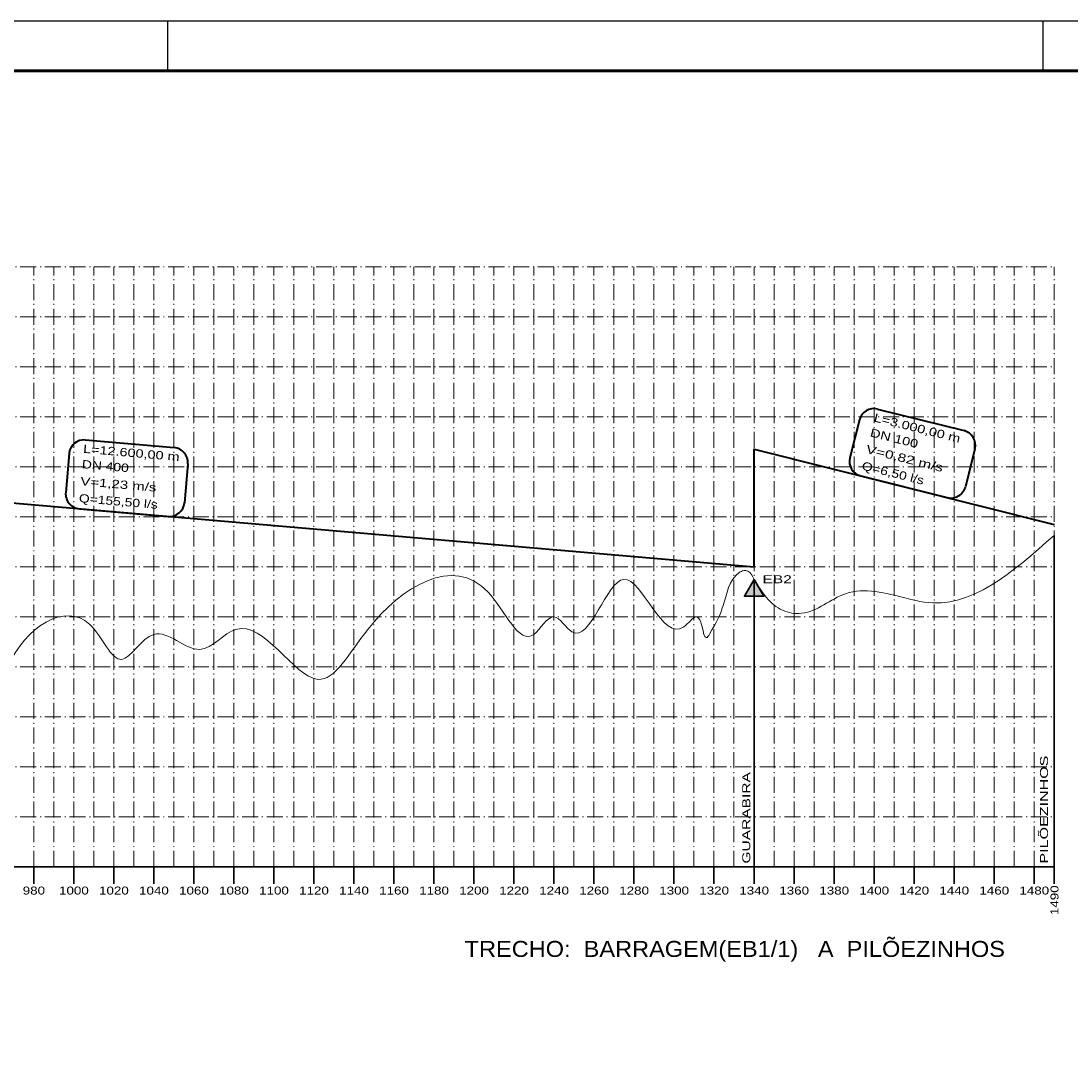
# Model space of a CAD drawing. Extents: x -4 to 42046, y -3 to 29697.
# Drawn here: x 22579 to 33074, y 19227 to 29697 of the extents above; entities that cross this region are included whole.
import ezdxf
from ezdxf.enums import TextEntityAlignment as Align

# ---------------------------------------------------------------- set-up
doc = ezdxf.new("R2010")
doc.units = 0
doc.header["$LTSCALE"] = 32
doc.linetypes.add('DOT_DASHED', pattern=[7.7, 5, -1.2, 0.3, -1.2])
for name, color, linetype, lineweight in [('1', 7, 'DOT_DASHED', 13), ('24', 7, 'Continuous', 35), ('55', 7, 'Continuous', 13), ('62', 7, 'Continuous', 13), ('63', 7, 'Continuous', 25), ('9', 7, 'Continuous', 40)]:
    doc.layers.add(name, color=color, linetype=linetype, lineweight=lineweight)

msp = doc.modelspace()

# ---------------------------------------------------------------- hatches: boundary and pattern name
at = {"layer": '62'}
msp.add_hatch(color=256, dxfattribs=at).paths.add_polyline_path([(29905.77, 24113.44), (30004.42, 23944.99), (29809.21, 23943.78)])

# ---------------------------------------------------------------- linework, layer by layer
at = {"layer": '1'}
for p, q in [((3105.77, 27238.44), (32905.77, 27238.44)), ((22705.77, 21238.44), (22705.77, 27238.44)), ((22905.77, 21238.44), (22905.77, 27238.44)), ((23105.77, 21238.44), (23105.77, 27238.44)), ((23305.77, 21238.44), (23305.77, 27238.44)), ((23505.77, 21238.44), (23505.77, 27238.44)), ((23705.77, 21238.44), (23705.77, 27238.44)), ((23905.77, 21238.44), (23905.77, 27238.44)), ((24105.77, 21238.44), (24105.77, 27238.44)), ((24305.77, 21238.44), (24305.77, 27238.44)), ((24505.77, 21238.44), (24505.77, 27238.44)), ((24705.77, 21238.44), (24705.77, 27238.44)), ((24905.77, 21238.44), (24905.77, 27238.44)), ((25105.77, 21238.44), (25105.77, 27238.44)), ((25305.77, 21238.44), (25305.77, 27238.44)), ((25505.77, 21238.44), (25505.77, 27238.44)), ((25705.77, 21238.44), (25705.77, 27238.44)), ((25905.77, 21238.44), (25905.77, 27238.44)), ((26105.77, 21238.44), (26105.77, 27238.44)), ((26305.77, 21238.44), (26305.77, 27238.44)), ((26505.77, 21238.44), (26505.77, 27238.44)), ((26705.77, 21238.44), (26705.77, 27238.44)), ((26905.77, 21238.44), (26905.77, 27238.44)), ((27105.77, 21238.44), (27105.77, 27238.44)), ((27305.77, 21238.44), (27305.77, 27238.44)), ((27505.77, 21238.44), (27505.77, 27238.44)), ((27705.77, 21238.44), (27705.77, 27238.44)), ((27905.77, 21238.44), (27905.77, 27238.44)), ((28105.77, 21238.44), (28105.77, 27238.44)), ((28305.77, 21238.44), (28305.77, 27238.44)), ((28505.77, 21238.44), (28505.77, 27238.44)), ((28705.77, 21238.44), (28705.77, 27238.44)), ((28905.77, 21238.44), (28905.77, 27238.44)), ((29105.77, 21238.44), (29105.77, 27238.44)), ((29305.77, 21238.44), (29305.77, 27238.44)), ((29505.77, 21238.44), (29505.77, 27238.44)), ((29705.77, 21238.44), (29705.77, 27238.44)), ((29905.77, 21238.44), (29905.77, 27238.44)), ((30105.77, 21238.44), (30105.77, 27238.44)), ((30305.77, 21238.44), (30305.77, 27238.44)), ((30505.77, 21238.44), (30505.77, 27238.44)), ((30705.77, 21238.44), (30705.77, 27238.44)), ((30905.77, 21238.44), (30905.77, 27238.44)), ((31105.77, 21238.44), (31105.77, 27238.44)), ((31305.77, 21238.44), (31305.77, 27238.44)), ((31505.77, 21238.44), (31505.77, 27238.44)), ((31705.77, 21238.44), (31705.77, 27238.44)), ((31905.77, 21238.44), (31905.77, 27238.44)), ((32105.77, 21238.44), (32105.77, 27238.44)), ((32305.77, 21238.44), (32305.77, 27238.44)), ((32505.77, 21238.44), (32505.77, 27238.44)), ((32705.77, 21238.44), (32705.77, 27238.44)), ((32905.77, 21238.44), (32905.77, 27238.44)), ((3105.77, 26738.44), (32905.77, 26738.44)), ((3105.77, 26238.44), (32905.77, 26238.44)), ((3105.77, 25738.44), (32905.77, 25738.44)), ((3105.77, 25238.44), (32905.77, 25238.44)), ((3105.77, 24738.44), (32905.77, 24738.44)), ((3105.77, 24238.44), (32905.77, 24238.44)), ((3105.77, 23738.44), (32905.77, 23738.44)), ((3105.77, 23238.44), (32905.77, 23238.44)), ((3105.77, 22738.44), (32905.77, 22738.44)), ((3105.77, 22238.44), (32905.77, 22238.44)), ((3105.77, 21738.44), (32905.77, 21738.44))]:
    msp.add_line(p, q, dxfattribs=at)
at = {"layer": '55', "lineweight": 35}
for p, q in [((32905.77, 24552.34), (32905.77, 21238.44)), ((29905.77, 24113.44), (29905.77, 21238.44))]:
    msp.add_line(p, q, dxfattribs=at)
at = {"layer": '55'}
for points in [[(29905.77, 24113.44), (30192.18, 23803.77), (30381.43, 23773.53), (30820.47, 23970.1), (31426.06, 23924.74), (31606.9, 23884.64), (32905.77, 24552.34)], [(3105.77, 22363.44), (3345.77, 22238.44), (3395.77, 22113.44), (3445.77, 22238.44), (3485.77, 22488.44), (3525.77, 22238.44), (3676.64, 22756.56), (3717.19, 22944.93), (3805.77, 23063.44), (3905.77, 22738.44), (3965.77, 22363.44), (4225.77, 23188.44), (4625.77, 22988.44), (5145.77, 21963.44), (6165.77, 22963.44), (6365.77, 22738.44), (6545.77, 22988.44), (6945.77, 23088.44), (7145.77, 23188.44), (7685.77, 23188.44), (8005.77, 22988.44), (8205.77, 22488.44), (8245.77, 22613.44), (8285.77, 22488.44), (8705.77, 22113.44), (9065.77, 22738.44), (9685.77, 23288.44), (10205.77, 23238.44), (10545.77, 23313.44), (11345.77, 23413.44), (11545.77, 23263.44), (12365.77, 23988.44), (12705.77, 23613.44), (12805.77, 23563.44), (13605.77, 23863.44), (13845.77, 23738.44), (13905.77, 23663.44), (14265.77, 24038.44), (14465.77, 24088.44), (14965.77, 23738.44), (15205.77, 23988.44), (15365.77, 23738.44), (15665.77, 23488.44), (15885.77, 23813.44), (16285.77, 23363.44), (16785.77, 22488.44), (16825.77, 22363.44), (16985.77, 22863.44), (17065.77, 22738.44), (17225.77, 22588.44), (17685.77, 22288.44), (17925.77, 22338.44), (18085.77, 22288.44), (18185.77, 22488.44), (18285.77, 22388.44), (18705.77, 22488.44), (18785.77, 22538.44), (18845.77, 22488.44), (19325.77, 22888.44), (19685.77, 22363.44), (20185.77, 22988.44), (20645.77, 23188.44), (21145.77, 22588.44), (21245.77, 22738.44), (21425.77, 22563.44), (21525.77, 22613.44), (21645.77, 22738.44), (21745.77, 22363.44), (21845.77, 22688.44), (22085.77, 22613.44), (22445.77, 23238.44), (23265.77, 23663.44), (23585.77, 23313.44), (23905.77, 23563.44), (24365.77, 23413.44), (24725.77, 23613.44), (25545.77, 23113.44), (26045.77, 23613.44), (27245.77, 23988.44), (27705.77, 23563.44), (27905.77, 23738.44), (28085.77, 23588.44), (28605.77, 24113.44), (29205.77, 23638.44), (29325.77, 23738.44), (29405.77, 23563.44)], [(29402.55, 23570.49), (29429.17, 23530.24), (29461.04, 23566.32), (29597.02, 23850.72), (29757.98, 24180.3), (29803.11, 24200.24), (29842.69, 24195.26), (29905.77, 24113.44)]]:
    msp.add_spline(points, degree=3, dxfattribs=at)
at = {"layer": '62', "lineweight": 35}
for p, q in [((22705.77, 21238.44), (22705.77, 21067.76)), ((23105.77, 21238.44), (23105.77, 21067.76)), ((23505.77, 21238.44), (23505.77, 21067.76)), ((23905.77, 21238.44), (23905.77, 21067.76)), ((24305.77, 21238.44), (24305.77, 21067.76)), ((24705.77, 21238.44), (24705.77, 21067.76)), ((25105.77, 21238.44), (25105.77, 21067.76)), ((25505.77, 21238.44), (25505.77, 21067.76)), ((25905.77, 21238.44), (25905.77, 21067.76)), ((26305.77, 21238.44), (26305.77, 21067.76)), ((26705.77, 21238.44), (26705.77, 21067.76)), ((27105.77, 21238.44), (27105.77, 21067.76)), ((27505.77, 21238.44), (27505.77, 21067.76)), ((27905.77, 21238.44), (27905.77, 21067.76)), ((28305.77, 21238.44), (28305.77, 21067.76)), ((28705.77, 21238.44), (28705.77, 21067.76)), ((29105.77, 21238.44), (29105.77, 21067.76)), ((29505.77, 21238.44), (29505.77, 21067.76)), ((29905.77, 21238.44), (29905.77, 21067.76)), ((29905.77, 21238.44), (32905.77, 21238.44)), ((30305.77, 21238.44), (30305.77, 21067.76)), ((30705.77, 21238.44), (30705.77, 21067.76)), ((31105.77, 21238.44), (31105.77, 21067.76)), ((31505.77, 21238.44), (31505.77, 21067.76)), ((31905.77, 21238.44), (31905.77, 21067.76)), ((32305.77, 21238.44), (32305.77, 21067.76)), ((32705.77, 21238.44), (32705.77, 21067.76)), ((32905.77, 21238.44), (32905.77, 21067.76))]:
    msp.add_line(p, q, dxfattribs=at)
msp.add_lwpolyline([(29905.77, 24113.44), (30004.42, 23944.99), (29809.21, 23943.78)], close=True, dxfattribs=at)
msp.add_lwpolyline([(3105.77, 21238.44), (10105.77, 21238.44), (29905.77, 21238.44)], dxfattribs=at)
at = {"layer": '63'}
for p, q in [((-4.21, 29697.03), (42045.8, 29697.03)), ((24045.8, 29197.03), (24045.8, 29697.03)), ((32795.79, 29197.03), (32795.79, 29697.03))]:
    msp.add_line(p, q, dxfattribs=at)
at = {"layer": '63', "lineweight": 60}
msp.add_lwpolyline([(1245.8, 29197.03), (41545.8, 29197.03), (41545.8, 497.03), (32795.79, 497.03)], dxfattribs=at)
at = {"layer": '9'}
for p, q in [((31141.29, 25816.69), (32005.48, 25600.36)), ((30959.36, 25707.6), (30864.59, 25329.02)), ((23221.25, 25507.27), (24108.81, 25430.79)), ((32114.57, 25418.43), (32019.8, 25039.85)), ((23058.93, 25370.7), (23025.42, 24981.88)), ((24245.38, 25268.46), (24211.88, 24879.64)), ((30973.68, 25147.08), (31837.86, 24930.76)), ((23161.99, 24819.56), (24049.55, 24743.07))]:
    msp.add_line(p, q, dxfattribs=at)
msp.add_lwpolyline([(3105.77, 26870.69), (4205.77, 26681.69), (17305.77, 25324.19), (29905.77, 24238.44), (29905.77, 25414.4), (32905.77, 24663.44)], dxfattribs=at)
for centre, start, end in [((31104.87, 25671.18), 75.94643, 165.94643), ((23208.37, 25357.82), 85.07494, 175.07494), ((31969.06, 25454.85), 345.94643, 75.94643), ((24095.93, 25281.34), 355.07494, 85.07494), ((31010.1, 25292.59), 165.94643, 255.94643), ((23174.87, 24969), 175.07494, 265.07494), ((31874.29, 25076.27), 255.94643, 345.94643), ((24062.43, 24892.52), 265.07494, 355.07494)]:
    msp.add_arc(centre, 150, start, end, dxfattribs=at)

# ---------------------------------------------------------------- texts
at = {"layer": '24', "width": 1.45}
msp.add_text('EB2', height=80, dxfattribs=at).set_placement((29990.82, 24074.5))
at = {"layer": '24'}
for s, width, p in [('PILÕEZINHOS', 1.5, (32844.77, 21271.36)), ('GUARABIRA', 1.45, (29868.45, 21271.36))]:
    msp.add_text(s, height=80, rotation=90, dxfattribs=dict(at, width=width)).set_placement(p)
for s, height, width, p in [('980', 80, 1.25, (22707.4, 20961.24)), ('1000', 80, 1.25, (23107.4, 20961.24)), ('1020', 80, 1.25, (23507.4, 20961.24)), ('1040', 80, 1.25, (23907.4, 20961.24)), ('1060', 80, 1.25, (24307.4, 20961.24)), ('1080', 80, 1.25, (24707.4, 20961.24)), ('1100', 80, 1.25, (25107.4, 20961.24)), ('1120', 80, 1.25, (25507.4, 20961.24)), ('1140', 80, 1.25, (25907.4, 20961.24)), ('1160', 80, 1.25, (26307.4, 20961.24)), ('1180', 80, 1.25, (26707.4, 20961.24)), ('1200', 80, 1.25, (27107.4, 20961.24)), ('1220', 80, 1.25, (27507.4, 20961.24)), ('1240', 80, 1.25, (27907.4, 20961.24)), ('1260', 80, 1.25, (28307.4, 20961.24)), ('1280', 80, 1.25, (28707.4, 20961.24)), ('1300', 80, 1.25, (29107.4, 20961.24)), ('1320', 80, 1.25, (29507.4, 20961.24)), ('1340', 80, 1.25, (29907.4, 20961.24)), ('1360', 80, 1.25, (30307.4, 20961.24)), ('1380', 80, 1.25, (30707.4, 20961.24)), ('1400', 80, 1.25, (31107.4, 20961.24)), ('1420', 80, 1.25, (31507.4, 20961.24)), ('1440', 80, 1.25, (31907.4, 20961.24)), ('1460', 80, 1.25, (32307.4, 20961.24)), ('1480', 80, 1.25, (32707.4, 20961.24)), ('TRECHO:  BARRAGEM(EB1/1)   A  PILÕEZINHOS', 160, 1.1, (29713.7, 20337.39))]:
    msp.add_text(s, height=height, dxfattribs=dict(at, width=width)).set_placement(p, align=Align.CENTER)
at = {"layer": '24', "width": 1.25}
msp.add_text('1490', height=80, rotation=90, dxfattribs=at).set_placement((32949.09, 20904.33), align=Align.CENTER)
at = {"layer": '9'}
for s, rotation, width, p in [('L=3.000,00 m', 345.946, 1.3, (31097.36, 25694.22)), ('DN 100', 345.946, 1.3, (31059.84, 25544.35)), ('L=12.600,00 m', 355.075, 1.3, (23197.3, 25379.39)), ('V=0,82 m/s', 345.946, 1.4, (31018.42, 25378.87)), ('DN 400', 355.075, 1.25, (23184.04, 25225.46)), ('Q=6,50 l/s', 345.946, 1.25, (30977, 25213.39)), ('V=1,23 m/s', 355.075, 1.35, (23169.39, 25055.5)), ('Q=155,50 l/s', 355.075, 1.25, (23154.75, 24885.54))]:
    msp.add_text(s, height=82.98, rotation=rotation, dxfattribs=dict(at, width=width)).set_placement(p)

doc.saveas('drawing.dxf')
